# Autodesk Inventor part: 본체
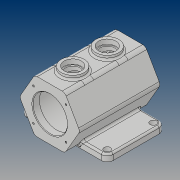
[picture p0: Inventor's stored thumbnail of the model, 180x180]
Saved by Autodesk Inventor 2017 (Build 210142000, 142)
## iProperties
Part Number: 본체
Material: 일반
Document SubType Name: Modeling
Designer: user
Density: 1 g/cm^3
Appearance: 기본값
Mass: 555.709 g
Surface Area: 1105.94 cm^2
Volume: 555.709 cm^3
Author: user
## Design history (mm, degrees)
sketch "스케치1" dims "d1" = 105
  geometry: L1 (26.25, 45.466)-(52.5, 0); L2 (52.5, 0)-(26.25, -45.466); L3 (26.25, -45.466)-(-26.25, -45.466); L4 (-26.25, -45.466)-(-52.5, 0); L5 (-52.5, 0)-(-26.25, 45.466); L6 (-26.25, 45.466)-(26.25, 45.466); C1 r 30 at (0, 0); 4 further points
  constraints: 12 end point, 3 coincident, 1 centre point, 1 horizontal alignment, 1 midpoint, 1 vertical alignment, 16 other
  dimensions: "d2" = 60 diameter of C1
extrude "돌출1" new body sketch "스케치1" stored distance "d3" = 140; taper "d4" = 0 deg
sketch "스케치2"
  geometry: C1 r 37.5 at (0, 0); 1 further point
  constraints: 1 centre point, 1 coincident
  dimensions: "d5" = 75 diameter of C1
extrude "돌출2" cut sketch "스케치2" stored distance "d6" = 116; taper "d7" = 0 deg
node "작업 평면1"
sketch "스케치3"
  geometry: L1 (26.25, -70)-(-26.25, -70) reference; C1 r 20 at (0, -30); C2 r 20 at (0, 30); 1 further point
  constraints: 2 centre point, 2 vertical alignment
  dimensions: "d9" = 40 diameter of C1; "d10" = 40 distance from line of C1.centre L1; "d11" = 40 diameter of C2; "d12" = 60 distance of C2.centre C1.centre
extrude "돌출3" join sketch "스케치3" stored distance "d13" = 116; taper "d14" = 0 deg
hole "구멍1" diameter "d17" = 25; stored, may be unused: countersink angle "d21" = 90 deg, drill point angle "d23" = 0 deg; dims "d15" = 10, "d16" = 10, "d18" = 6, "d19" = 30, "d20" = 8, "d22" = 8
hole "구멍2" diameter "d26" = 25; stored, may be unused: countersink angle "d30" = 90 deg, drill point angle "d32" = 0 deg; dims "d24" = 10, "d25" = 10, "d27" = 6, "d28" = 30, "d29" = 8, "d31" = 8
node "작업 평면2"
sketch "스케치4"
  geometry: L1 (75, 45)-(-75, 45); L2 (-75, 45)-(-75, -55); L3 (-75, -55)-(75, -55); L4 (26.25, 70)-(52.5, 70) reference; L5 (52.5, -70)-(26.25, -70) reference; L6 (75, 45)-(75, -55); 2 further points
  constraints: 8 end point, 1 horizontal, 1 midpoint, 1 parallel, 1 perpendicular, 1 vertical, 1 vertical alignment
  dimensions: "d34" = 150 distance of L2.end L3.end; "d36" = 25 distance between parallel lines of L4 L1; "d37" = 15 distance between parallel lines of L3 L5
extrude "돌출4" join sketch "스케치4" distance "d38" = 12; taper "d39" = 0 deg
fillet "모깎기1" dims "d40" = 10
sketch "스케치5"
  geometry: A1 r 10 centre (-65, 45) between (-65, 55) and (-75, 45) reference; A2 r 10 centre (-65, -35) between (-75, -35) and (-65, -45) reference; A3 r 10 centre (65, -35) between (65, -45) and (75, -35) reference; A4 r 10 centre (65, 45) between (75, 45) and (65, 55) reference; 1 further point
hole "구멍3" sketch "스케치5" at (-65, 45), (-65, -35), (65, -35), (65, 45) diameter "d41" = 11; stored, may be unused: countersink angle "d45" = 90 deg, drill point angle "d47" = 0 deg; dims "d42" = 6, "d43" = 30, "d44" = 8, "d46" = 8
sketch "스케치6" dims "d49" = 80
  geometry: L1 (0, 0)-(-28.284, 28.284); L2 (0, 0)-(0, 77.128); 1 further point
  constraints: 4 end point, 1 coincident, 1 vertical, 3 other
  dimensions: "d48" = 45 deg angle of L1 L2
hole "구멍4" sketch "스케치6" at (-28.284, 28.284) diameter "d50" = 3.242; stored, may be unused: countersink angle "d54" = 90 deg, drill point angle "d56" = 118 deg; dims "d51" = 8, "d52" = 30, "d53" = 8, "d55" = 10
sketch "스케치7"
  geometry: 2 further points
  constraints: 1 vertical alignment
  dimensions: "d60" = 40 distance of point (0, 40) point (0, 0)
hole "구멍5" sketch "스케치7" at (0, 40) diameter "d61" = 3.242; stored, may be unused: countersink angle "d65" = 90 deg, drill point angle "d67" = 118 deg; dims "d62" = 8, "d63" = 30, "d64" = 8, "d66" = 10
sketch "스케치8"
  geometry: L1 (-65, -45)-(-30.561, -45) reference; L2 (-75, 45)-(-75, -35) reference; 2 further points
  constraints: 1 other
  dimensions: "d71" = 50 distance from line of point (-61, 5) L1; "d72" = 14 distance from line of point (-61, 5) L2
feature "엠보싱1" sketch "스케치8" dims "d73" = 0.5, "d74" = 0
chamfer "모따기1" distance "d75" = 1; stored, may be unused: second distance "d76" = 2, angle "d77" = 45 deg
fillet "모깎기2" dims "d78" = 3
fillet "모깎기3" dims "d79" = 5
chamfer "모따기2" distance "d80" = 1; stored, may be unused: second distance "d81" = 2, angle "d82" = 45 deg
fillet "모깎기4" dims "d83" = 8
node "솔리드1"
pattern_circular "원형 패턴1" dims angle "d58" = 360 deg
pattern_circular "원형 패턴2" dims angle "d69" = 360 deg
other parameters: "d8" = 52.5
